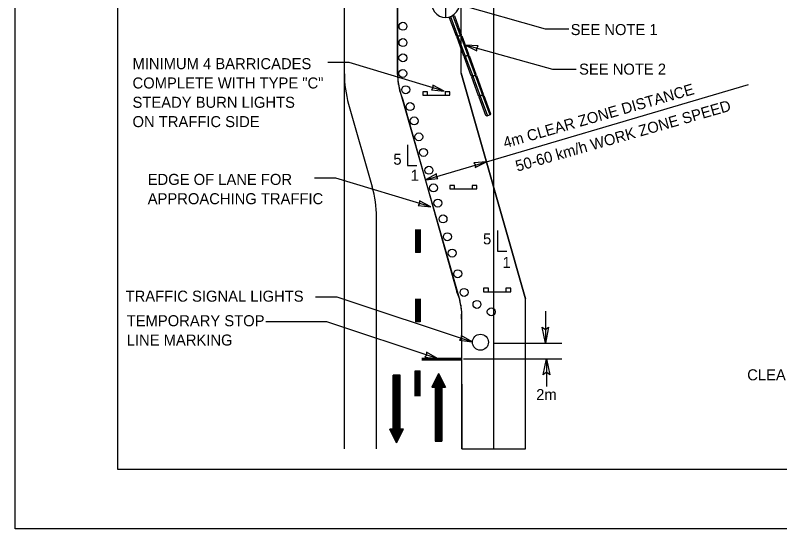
# Model space of a CAD drawing. Extents: x 2427 to 2645, y -255 to 24.
# Drawn here: x 2429 to 2567.5, y -255 to -162 of the extents above; entities that cross this region are included whole.
import ezdxf

# ---------------------------------------------------------------- set-up
doc = ezdxf.new("R2010")
doc.units = 0
for name, color, linetype in [('Level 10', 7, 'Continuous'), ('Level 17', 7, 'Continuous'), ('Level 22', 7, 'Continuous'), ('Level 4', 7, 'Continuous'), ('Level 44', 7, 'Continuous'), ('Level 5', 7, 'Continuous'), ('Level 60', 7, 'Continuous')]:
    doc.layers.add(name, color=color, linetype=linetype)

# ---------------------------------------------------------------- blocks, each defined once
blk = doc.blocks.new('TAH01')
at = {"layer": 'Level 5'}
blk.add_lwpolyline([(0, 0), (-3, -0.62), (-2.504, 0), (-3, 0.62)], close=True, dxfattribs=at)
blk = doc.blocks.new('LT1')
at = {"layer": 'Level 5'}
blk.add_blockref('TAH01', (0, 0), dxfattribs=at)
blk = doc.blocks.new('arrow')
at = {"layer": 'Level 60'}
blk.add_lwpolyline([(0.6, 0.12), (0, 0), (0.6, -0.12), (0.56, 0)], close=True, dxfattribs=at)

msp = doc.modelspace()

# ---------------------------------------------------------------- linework, layer by layer
at = {"layer": 'Level 10'}
for p, q in [((2488.6, -172.56), (2488.6, -48.35)), ((2498.24, -172.68), (2498.19, -55.44)), ((2515.69, -240.54), (2515.69, -129.21)), ((2488.6, -240.54), (2488.6, -148.86)), ((2509.79, -172.46), (2521.44, -213.34)), ((2498.62, -175.42), (2509.5, -213.61)), ((2499.21, -177.27), (2508.98, -212.07)), ((2489.37, -178.05), (2493.64, -193.04)), ((2494.41, -240.54), (2494.41, -198.52)), ((2525.02, -215.57), (2525.02, -221.34)), ((2509.89, -240.54), (2509.89, -216.35)), ((2515.78, -221.34), (2528, -221.34)), ((2509.71, -224.16), (2502.63, -224.16)), ((2509.71, -224.16), (2502.63, -224.16)), ((2509.71, -224.26), (2502.63, -224.26)), ((2509.71, -224.26), (2502.63, -224.26)), ((2509.71, -224.26), (2502.63, -224.26)), ((2509.71, -224.36), (2502.63, -224.36)), ((2509.71, -224.36), (2502.63, -224.36)), ((2510.19, -224.21), (2528, -224.21)), ((2525.2, -224.3), (2525.2, -229.2)), ((2509.71, -224.45), (2502.63, -224.45)), ((2497.46, -236.95), (2497.46, -227.14)), ((2498.69, -227.14), (2497.46, -227.14)), ((2497.46, -238.18), (2497.46, -227.14)), ((2497.62, -238.48), (2497.62, -227.14)), ((2497.77, -238.79), (2497.77, -227.14)), ((2497.92, -239.1), (2497.92, -227.14)), ((2498.07, -239.41), (2498.07, -227.14)), ((2498.23, -239.1), (2498.23, -227.14)), ((2498.38, -238.79), (2498.38, -227.14)), ((2498.54, -238.48), (2498.54, -227.14)), ((2498.69, -236.95), (2498.69, -227.14)), ((2498.69, -238.18), (2498.69, -227.14)), ((2505.68, -226.87), (2504.45, -229.32)), ((2505.68, -226.87), (2505.68, -239.14)), ((2505.68, -226.87), (2506.9, -229.32)), ((2504.91, -228.4), (2504.91, -229.32)), ((2505.06, -228.09), (2505.06, -239.14)), ((2505.22, -227.79), (2505.22, -239.14)), ((2505.37, -227.48), (2505.37, -239.14)), ((2505.53, -227.17), (2505.53, -239.14)), ((2505.83, -227.17), (2505.83, -239.14)), ((2505.98, -227.48), (2505.98, -239.14)), ((2506.14, -227.79), (2506.14, -239.14)), ((2506.29, -228.09), (2506.29, -239.14)), ((2506.44, -228.4), (2506.44, -229.32)), ((2504.45, -229.32), (2505.06, -229.32)), ((2504.6, -229.01), (2504.6, -229.32)), ((2504.76, -228.71), (2504.76, -229.32)), ((2505.06, -229.32), (2505.06, -239.14)), ((2506.29, -229.32), (2506.29, -239.14)), ((2506.29, -229.32), (2506.9, -229.32)), ((2506.6, -228.71), (2506.6, -229.32)), ((2506.75, -229.01), (2506.75, -229.32)), ((2498.07, -239.41), (2496.85, -236.95)), ((2497.46, -236.95), (2496.85, -236.95)), ((2497, -237.26), (2497, -236.95)), ((2497.16, -237.57), (2497.16, -236.95)), ((2497.31, -237.87), (2497.31, -236.95)), ((2498.07, -239.41), (2499.3, -236.95)), ((2499.3, -236.95), (2498.69, -236.95)), ((2498.84, -237.87), (2498.84, -236.95)), ((2499, -237.57), (2499, -236.95)), ((2499.15, -237.26), (2499.15, -236.95)), ((2505.06, -239.14), (2506.29, -239.14))]:
    msp.add_line(p, q, dxfattribs=at)
msp.add_lwpolyline([(2509.8, -217.04), (2509.89, -240.54), (2521.44, -240.54), (2521.44, -213.34), (2509.79, -172.46), (2509.77, -129.21), (2498.32, -129.19), (2498.24, -172.95), (2498.38, -174.49)], dxfattribs=at)
for centre in [(2499.22, -163.94), (2499.22, -166.9), (2499.21, -169.66), (2499.19, -172.5), (2499.73, -175.45), (2500.51, -178.49), (2501.25, -181.09), (2502.09, -183.98), (2502.94, -186.81), (2503.92, -190.03), (2504.75, -193.24), (2505.54, -195.98), (2506.48, -198.86), (2507.27, -202.09), (2508.13, -205.04), (2509.14, -208.78), (2510.29, -212.17), (2512.63, -214.35), (2515.22, -215.69)]:
    msp.add_circle(centre, 0.718, dxfattribs=at)
for centre, radius, start, end in [((2508.6, -172.56), 20, 180, 195.9097), ((2508.24, -172.68), 10, 180.023, 195.9097), ((2508.28, -173.04), 10, 188.3439, 204.9857), ((2474.41, -198.52), 20, 360, 15.9097), ((2500.55, -216.01), 9.31, 353.6691, 25.0725), ((2499.89, -216.35), 10, 0, 15.9097)]:
    msp.add_arc(centre, radius, start, end, dxfattribs=at)
at = {"layer": 'Level 17'}
for p, q in [((2428.98, -254.99), (2428.98, 24.01)), ((2644.98, -254.99), (2428.98, -254.99))]:
    msp.add_line(p, q, dxfattribs=at)
at = {"layer": 'Level 22'}
for p, q in [((2447.52, 12.32), (2447.52, -244.18)), ((2447.52, -244.18), (2634.98, -244.18))]:
    msp.add_line(p, q, dxfattribs=at)
at = {"layer": 'Level 4'}
for p, q in [((2506.94, -158.69), (2506.94, -162.38)), ((2507.74, -162.22), (2508.36, -162)), ((2508.27, -162.03), (2509.6, -165.63)), ((2508.53, -162.07), (2508.36, -162)), ((2507.66, -162.39), (2507.74, -162.22)), ((2508.9, -165.75), (2507.66, -162.39)), ((2507.83, -162.19), (2509.16, -165.79)), ((2508.53, -162.07), (2509.77, -165.43)), ((2509.07, -165.82), (2508.9, -165.75)), ((2509.02, -165.99), (2509.09, -165.82)), ((2510.26, -169.34), (2509.02, -165.99)), ((2509.69, -165.59), (2509.07, -165.82)), ((2509.09, -165.82), (2509.72, -165.59)), ((2509.19, -165.79), (2510.52, -169.39)), ((2509.62, -165.63), (2510.95, -169.23)), ((2509.77, -165.43), (2509.69, -165.59)), ((2509.88, -165.67), (2509.72, -165.59)), ((2509.88, -165.67), (2511.12, -169.02)), ((2510.43, -169.42), (2510.26, -169.34)), ((2510.35, -169.59), (2510.42, -169.42)), ((2511.59, -172.94), (2510.35, -169.59)), ((2510.42, -169.42), (2511.05, -169.19)), ((2511.05, -169.19), (2510.43, -169.42)), ((2510.52, -169.39), (2511.85, -172.98)), ((2510.95, -169.23), (2512.28, -172.83)), ((2511.12, -169.02), (2511.05, -169.19)), ((2511.21, -169.27), (2511.05, -169.19)), ((2511.21, -169.27), (2512.45, -172.62)), ((2511.76, -173.02), (2511.59, -172.94)), ((2511.68, -173.19), (2511.75, -173.02)), ((2511.75, -173.02), (2512.38, -172.79)), ((2512.38, -172.79), (2511.76, -173.02)), ((2511.85, -172.98), (2513.18, -176.58)), ((2512.28, -172.83), (2513.61, -176.43)), ((2512.45, -172.62), (2512.38, -172.79)), ((2512.54, -172.87), (2512.38, -172.79)), ((2512.54, -172.87), (2513.78, -176.22)), ((2512.92, -176.54), (2511.68, -173.19)), ((2513.09, -176.62), (2512.92, -176.54)), ((2513.01, -176.79), (2513.08, -176.62)), ((2514.25, -180.14), (2513.01, -176.79)), ((2513.08, -176.62), (2513.71, -176.39)), ((2513.71, -176.39), (2513.09, -176.62)), ((2513.18, -176.58), (2514.51, -180.18)), ((2513.61, -176.42), (2514.94, -180.02)), ((2513.78, -176.22), (2513.71, -176.39)), ((2513.87, -176.47), (2513.71, -176.39)), ((2513.87, -176.47), (2515.11, -179.82)), ((2515.04, -179.99), (2514.42, -180.22)), ((2515.11, -179.82), (2515.04, -179.99)), ((2514.42, -180.22), (2514.25, -180.14))]:
    msp.add_line(p, q, dxfattribs=at)
msp.add_ellipse((2506.94, -158.68), major_axis=(0, -3.7), ratio=0.758621, start_param=4.716532, end_param=7.849839, dxfattribs=at)
at = {"layer": 'Level 44'}
for p, q in [((2502.36, -204.94), (2501.49, -204.94)), ((2502.36, -217.49), (2501.49, -217.49)), ((2501.46, -226.39), (2502.33, -226.39))]:
    msp.add_line(p, q, dxfattribs=at)
for points in [[(2501.49, -200.75), (2501.49, -204.94)], [(2501.63, -200.75), (2501.63, -204.94)], [(2501.78, -200.75), (2501.78, -204.94)], [(2501.92, -200.75), (2501.92, -204.94)], [(2502.07, -200.75), (2502.07, -204.94)], [(2502.21, -200.75), (2502.21, -204.94)], [(2502.36, -200.75), (2502.36, -204.94)], [(2501.49, -213.31), (2501.49, -217.49)], [(2501.63, -213.31), (2501.63, -217.49)], [(2501.78, -213.31), (2501.78, -217.49)], [(2501.92, -213.31), (2501.92, -217.49)], [(2502.07, -213.31), (2502.07, -217.49)], [(2502.21, -213.31), (2502.21, -217.49)], [(2502.36, -213.31), (2502.36, -217.49)], [(2501.46, -230.95), (2501.46, -226.39)], [(2501.61, -230.95), (2501.61, -226.39)], [(2501.75, -230.95), (2501.75, -226.39)], [(2501.9, -230.95), (2501.9, -226.39)], [(2502.04, -230.95), (2502.04, -226.39)], [(2502.19, -230.95), (2502.19, -226.39)], [(2502.33, -230.95), (2502.33, -226.39)]]:
    msp.add_lwpolyline(points, dxfattribs=at)
msp.add_circle((2513.25, -221.19), 1.45, dxfattribs=at)
at = {"layer": 'Level 5'}
for p, q in [((2509.79, -172.46), (2509.77, -129.21)), ((2489.45, -170.51), (2485.61, -170.51)), ((2503.28, -191.76), (2561.8, -174.47)), ((2503.69, -175.8), (2502.82, -175.8)), ((2502.82, -175.8), (2502.82, -176.42)), ((2503.69, -176.41), (2503.69, -175.8)), ((2507.74, -175.8), (2506.87, -175.8)), ((2506.87, -175.8), (2506.87, -176.42)), ((2507.74, -176.42), (2507.74, -175.8)), ((2502.82, -176.42), (2507.74, -176.42)), ((2500.02, -185.41), (2500.02, -189.17)), ((2500.02, -189.17), (2501.73, -189.17)), ((2487.04, -191.47), (2483.2, -191.47)), ((2508.58, -192.8), (2507.7, -192.8)), ((2507.7, -192.8), (2507.7, -193.41)), ((2507.7, -193.41), (2512.63, -193.41)), ((2508.58, -193.41), (2508.58, -192.8)), ((2512.63, -192.8), (2511.76, -192.8)), ((2511.76, -192.8), (2511.76, -193.41)), ((2512.63, -193.41), (2512.63, -192.8)), ((2516.32, -200.96), (2516.32, -204.72)), ((2516.32, -204.72), (2518.03, -204.72)), ((2514.7, -211.43), (2513.83, -211.43)), ((2513.83, -211.43), (2513.83, -212.04)), ((2514.7, -212.04), (2514.7, -211.43)), ((2518.76, -211.43), (2517.88, -211.42)), ((2517.88, -211.43), (2517.88, -212.04)), ((2518.76, -212.04), (2518.76, -211.43)), ((2513.83, -212.04), (2518.76, -212.04)), ((2521.44, -240.54), (2521.44, -213.34))]:
    msp.add_line(p, q, dxfattribs=at)
for points in [[(2529.3, -164.45), (2525.07, -164.45), (2509.28, -160.01)], [(2530.59, -171.78), (2526.36, -171.78), (2510.57, -167.34)], [(2506.67, -175.71), (2489.45, -170.51)], [(2504.25, -196.67), (2487.04, -191.47)], [(2483.4, -212.98), (2487.24, -212.98), (2511.73, -221.13)], [(2474.38, -217.45), (2485.37, -217.45), (2505.38, -224.1)]]:
    msp.add_lwpolyline(points, dxfattribs=at)

# ---------------------------------------------------------------- block references
for name, p, xscale, yscale, rotation in [('arrow', (2510.57, -167.34), 3.750000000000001, 3.7500000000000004, -15.697792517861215), ('arrow', (2506.67, -175.71), 3.75, 3.7500000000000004, 163.1852984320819), ('arrow', (2514.35, -188.49), 3.7499999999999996, 3.7500000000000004, -163.54106952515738), ('arrow', (2503.28, -191.76), 3.7499999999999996, 3.7500000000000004, 16.458930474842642), ('arrow', (2504.25, -196.67), 3.75, 3.7500000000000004, 163.1852984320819), ('LT1', (2525.02, -221.34), 0.9676, 0.9676, -90), ('arrow', (2511.73, -221.13), 3.7500000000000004, 3.7500000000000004, 161.60666326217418), ('arrow', (2505.45, -224.16), 3.7500000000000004, 3.7500000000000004, 161.60666326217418), ('LT1', (2525.25, -224.2), 0.9676, 0.9676, 90)]:
    msp.add_blockref(name, p, dxfattribs=dict(at, xscale=xscale, yscale=yscale, rotation=rotation))

# ---------------------------------------------------------------- texts
at = {"layer": 'Level 44'}
msp.add_text('        CLEAR ZONE APPLICATION FOR WORK AREA', height=2, dxfattribs=at).set_placement((2555.65, -228.1))
at = {"layer": 'Level 5'}
for s, p in [('SEE NOTE 1', (2529.61, -165.54)), ('MINIMUM 4 BARRICADES', (2450.22, -171.72)), ('SEE NOTE 2', (2531.13, -172.71)), ('COMPLETE WITH TYPE "C" ', (2450.22, -175.22)), ('STEADY BURN LIGHTS', (2450.22, -178.72)), ('ON TRAFFIC SIDE', (2450.22, -182.22)), ('5', (2497.48, -189.03)), ('EDGE OF LANE FOR', (2452.97, -192.69)), ('1', (2500.62, -191.95)), ('APPROACHING TRAFFIC', (2452.97, -196.19)), ('5', (2513.73, -203.46)), ('1', (2517.25, -207.74)), ('TRAFFIC SIGNAL LIGHTS', (2448.97, -213.85)), ('TEMPORARY STOP', (2449.17, -218.3)), ('LINE MARKING', (2449.17, -221.8)), ('2m', (2523.36, -231.68))]:
    msp.add_text(s, height=2, dxfattribs=at).set_placement(p)
for s, p in [('4m CLEAR ZONE DISTANCE', (2517.71, -186.05)), ('50-60 km/h WORK ZONE SPEED', (2519.94, -190.3))]:
    msp.add_text(s, height=2, rotation=15.9427, dxfattribs=at).set_placement(p)

doc.saveas('drawing.dxf')
